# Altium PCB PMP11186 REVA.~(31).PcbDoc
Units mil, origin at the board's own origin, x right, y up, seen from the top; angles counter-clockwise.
Board outline 5750 x 3370 mil, 4 copper layers (Top Layer, Signal Layer 1, Signal Layer 2, Bottom Layer), stack 85.4 mil thick; 92 components, 39 nets, 228 pads, 139 vias.
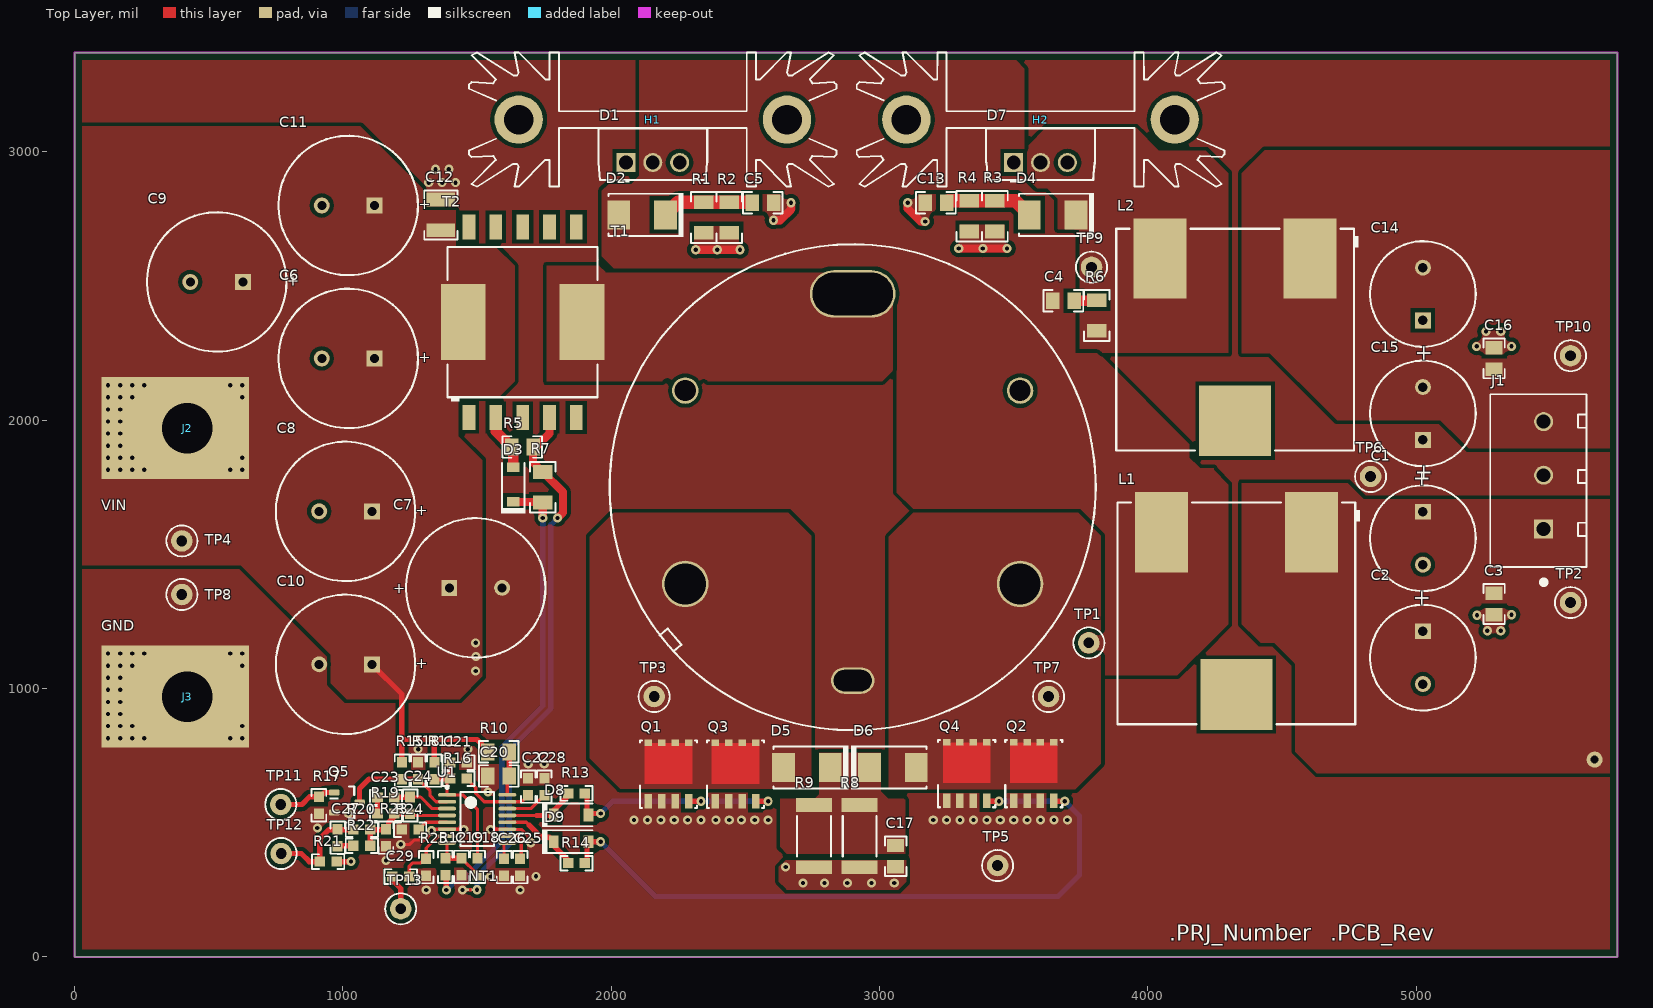
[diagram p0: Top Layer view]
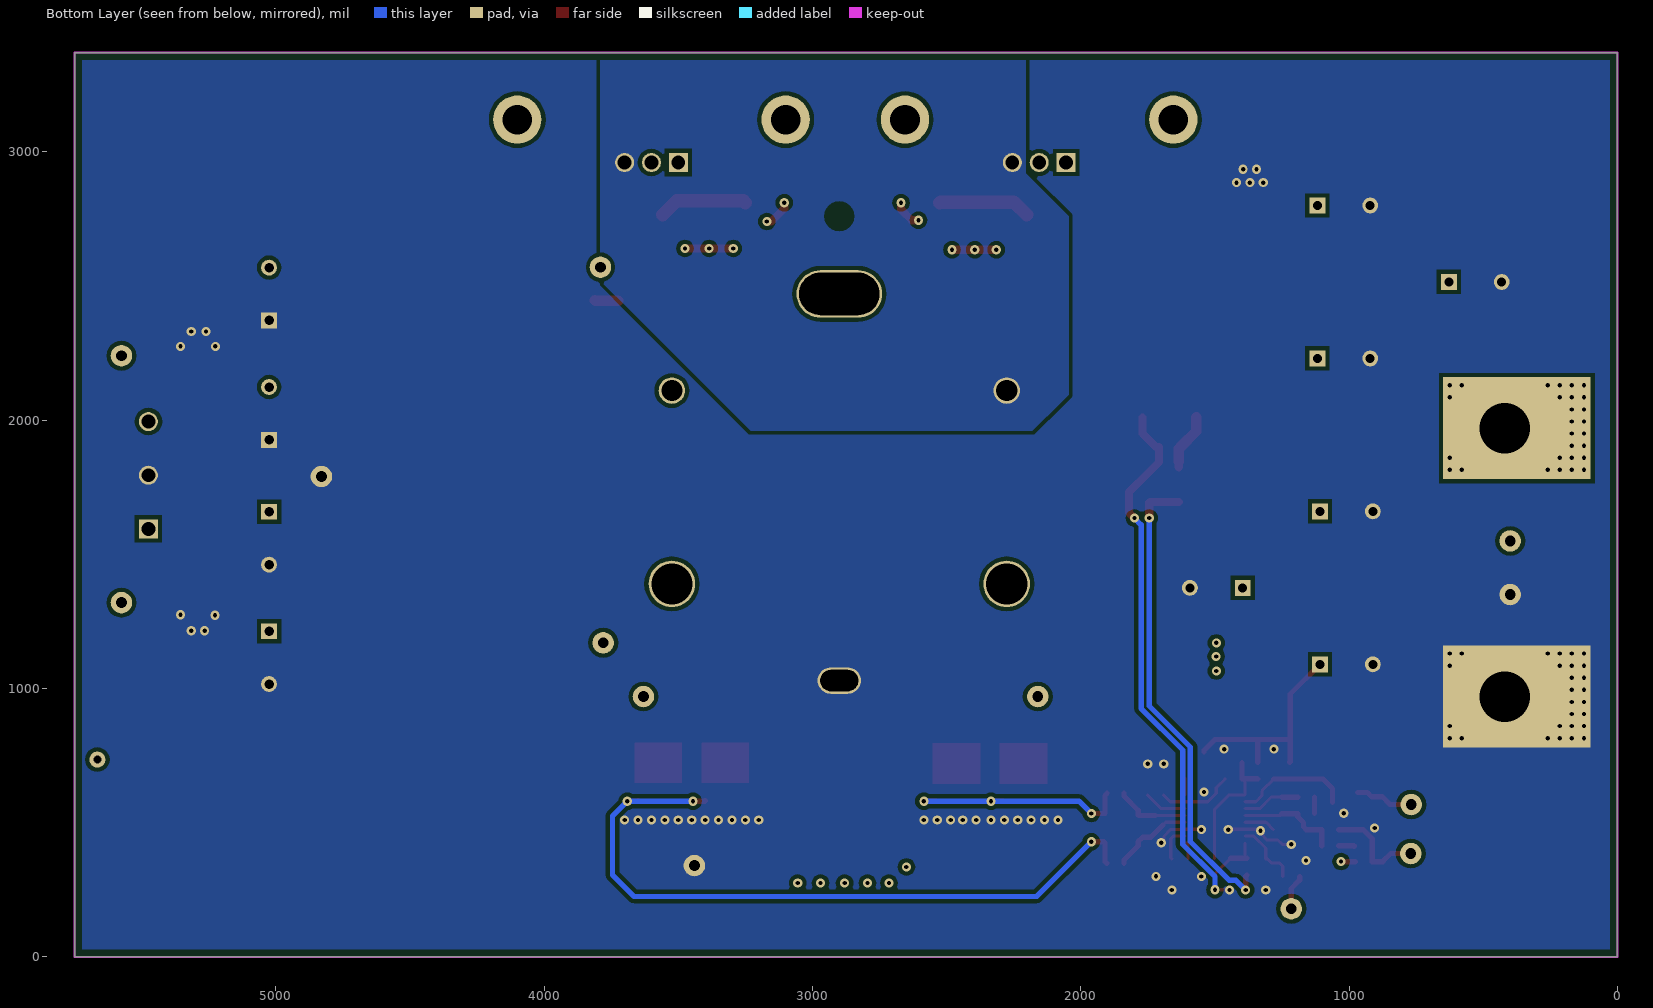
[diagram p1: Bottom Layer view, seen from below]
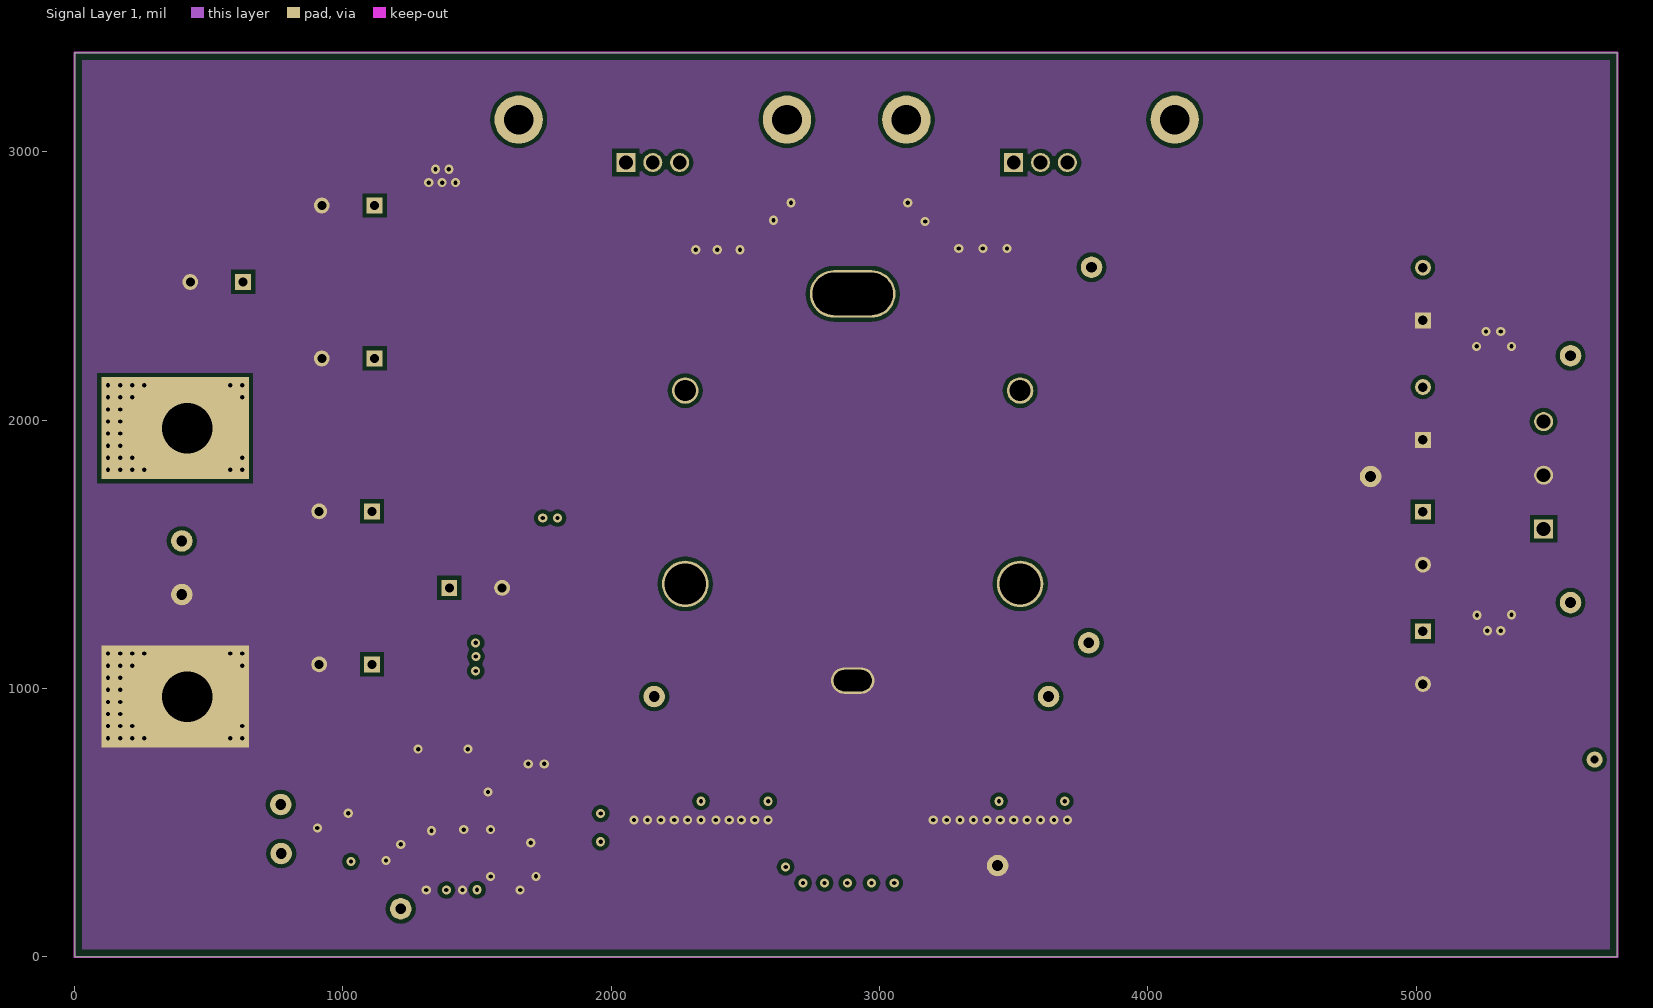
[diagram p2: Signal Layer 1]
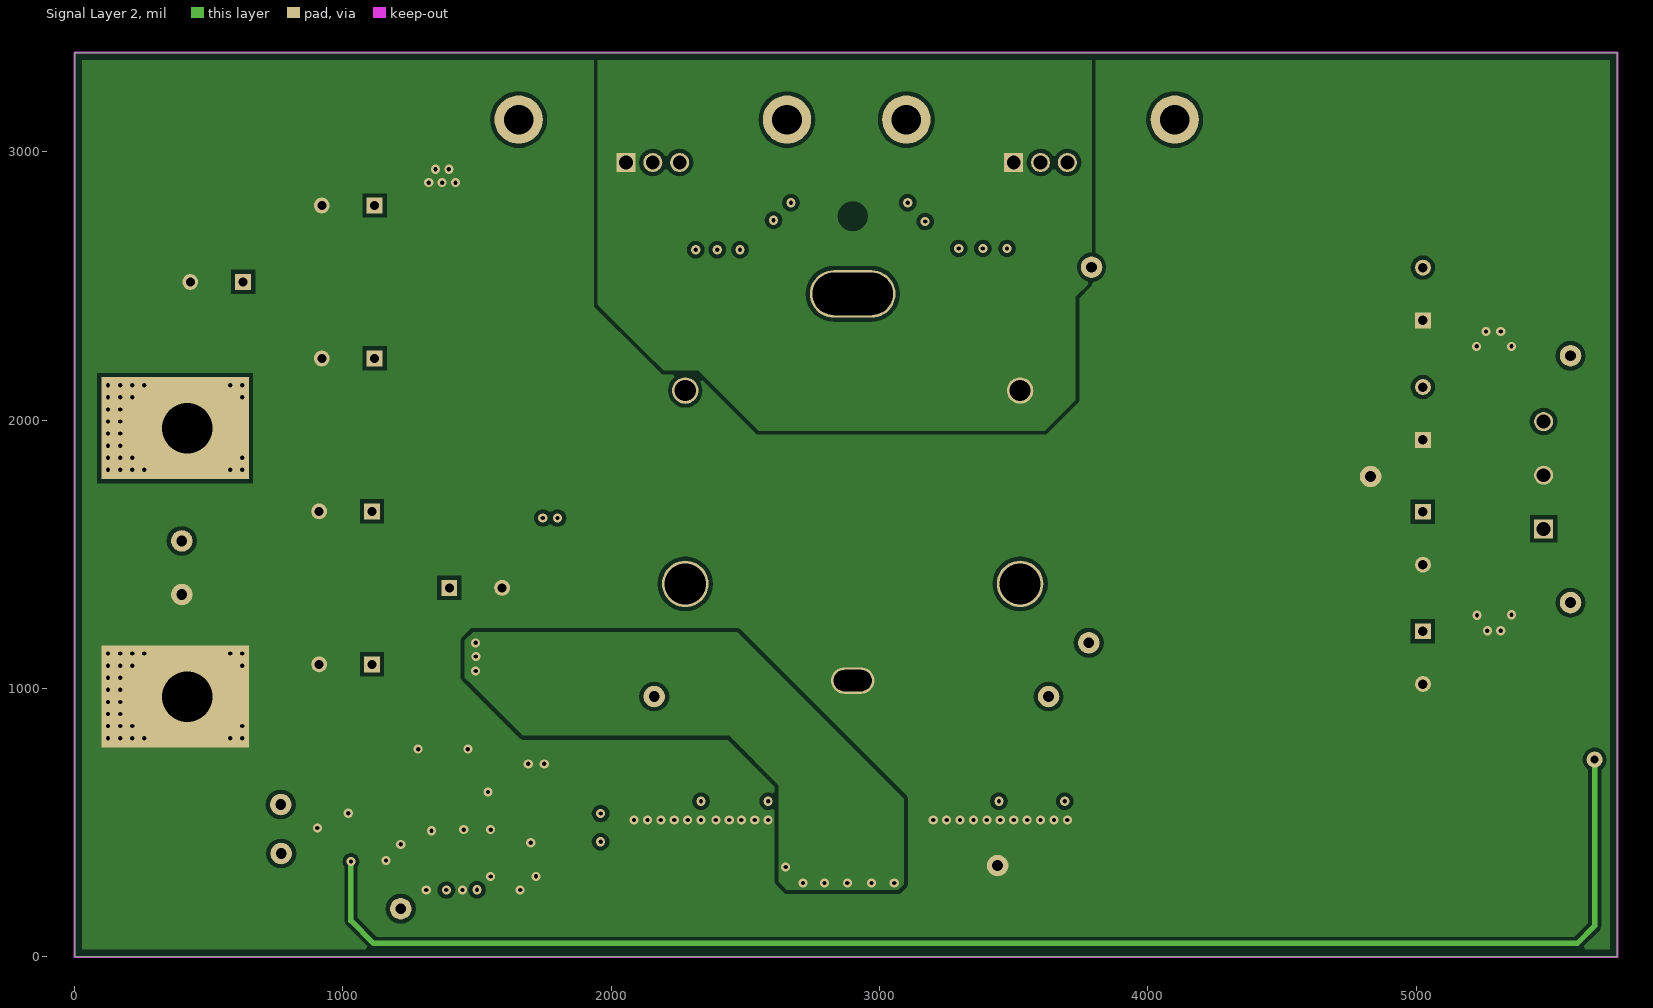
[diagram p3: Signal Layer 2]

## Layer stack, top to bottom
Top Solder: solder mask 0.4, Solder Resist, Dk 3.5
Top Layer: signal copper 2.8
Dielectric1: core 59.2, FR-4, Dk 4.8
Signal Layer 1: signal copper 2.8
Dielectric 3: prepreg 5, Dk 4.2
Signal Layer 2: signal copper 2.8
Dielectric 2: core 10, Dk 4.2
Bottom Layer: signal copper 2.8
Bottom Solder: solder mask 0.4, Solder Resist, Dk 3.5

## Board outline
0,0 5750,0 5750,3370 0,3370

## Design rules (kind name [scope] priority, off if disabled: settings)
AcuteAngle [All] p1: minimum=4.50000000000000E+0001 checktracksonly=FALSE
AssemblyTestPointUsage [All] p1: valid=2
Clearance Clearance_Keepouts [((IsTrack Or IsArc) And Not InPoly) And IsFree and IsKeepOut vs ((IsTrack Or IsArc) And Not InPoly) And IsFree and IsKeepOut] p1: gap=0
Clearance Clearance_BoardEdge_MountingHoles [OnCopper and InComponentClass('Mounting Holes') vs IsKeepOut] p2: gap=40
Clearance Clearance_BoardEdge_Poly [OnCopper and InPoly vs IsKeepOut] p3: gap=25
Clearance Clearance_BoardEdge [OnCopper and Not InComponentClass('Logo') and not InComponentClass('FiducialMark') and not InRegion(1000,500,4000,800) and Not IsKeepout vs IsKeepOut] p4: gap=25
Clearance Clearance_Poly [InPolygon] p5: gap=15
Clearance [All] p6: gap=7.87
ComponentClearance ComponentClearance_MountingHoles_FiducialMarks [InComponentClass('Mounting Holes') vs InComponentClass('FiducialMark')] p1: gap=50 collisioncheckmode=3 verticalgap=10 showdistances=FALSE
ComponentClearance ComponentClearance_Shunt [InComponentClass('Header') vs InComponentClass('Shunt')] p2: gap=0 collisioncheckmode=3 verticalgap=0 showdistances=FALSE
ComponentClearance ComponentClearance_Logo [InComponentClass('Logo')] p3: gap=50 collisioncheckmode=3 verticalgap=10 showdistances=FALSE
ComponentClearance ComponentClearance_ScrewToNut [(HasFootprint('NY PMS 440 0025 PH')) vs (HasFootprint('Keystone_1902C'))] p4: gap=5 collisioncheckmode=3 verticalgap=10 showdistances=FALSE
ComponentClearance ComponentClearance_MountingHoles [InComponentClass('Mounting Holes')] p5: gap=150 collisioncheckmode=3 verticalgap=100000 showdistances=FALSE
ComponentClearance ComponentClearance_SmallPassives [HasFootprint('0201*') or HasFootprint('0402*') or HasFootprint('0508') or HasFootprint('0603*') or HasFootprint('0612') or HasFootprint('0805*') or HasFootprint('0815*') or HasFootprint('0830*') or HasFootprint('1206*') or HasFootprint('1210*') or HasFootprint('1808*') or HasFootprint('1812*') or HasFootprint('1825*') or HasFootprint('2010*') or HasFootprint('2220*') or HasFootprint('2225*') or HasFootprint('2512*') or HasFootprint('2728*') or HasFootprint('3518*') vs HasFootprint('0201*') or HasFootprint('0402*') or HasFootprint('0508') or HasFootprint('0603*') or HasFootprint('0612') or HasFootprint('0805*') or HasFootprint('0815*') or HasFootprint('0830*') or HasFootprint('1206*') or HasFootprint('1210*') or HasFootprint('1808*') or HasFootprint('1812*') or HasFootprint('1825*') or HasFootprint('2010*') or HasFootprint('2220*') or HasFootprint('2225*') or HasFootprint('2512*') or HasFootprint('2728*') or HasFootprint('3518*')] p6: gap=15 collisioncheckmode=3 verticalgap=10 showdistances=FALSE
ComponentClearance ComponentClearance_THtoSMT [IsThruComponent vs IsSMTComponent] p7: gap=25 collisioncheckmode=3 verticalgap=30 showdistances=FALSE
ComponentClearance ComponentClearance_THtoTH [IsThruComponent vs IsThruComponent] p8: gap=25 collisioncheckmode=3 verticalgap=30 showdistances=FALSE
ComponentClearance [All] p9: gap=25 collisioncheckmode=3 verticalgap=10 showdistances=FALSE
DiffPairsRouting [All] p1: maxlimit=100 minlimit=10 mostfreqgap=10 toplayer_minwidth=15 toplayer_maxwidth=15 toplayer_prefwidth=15 midlayer1_minwidth=15 midlayer1_maxwidth=15 midlayer1_prefwidth=15 midlayer2_minwidth=15 midlayer2_maxwidth=15 midlayer2_prefwidth=15 bottomlayer_minwidth=15 bottomlayer_maxwidth=15 bottomlayer_prefwidth=15 maxuncoupledlength=1000
FabricationTestPointUsage TestPointUsage [All] p1: valid=2 allowmultiple=FALSE
FabricationTestpoint Testpoint [All] p1: side=3 testpointundercomponent=TRUE minsize=40 maxsize=100 preferedsize=60 minholesize=0 maxholesize=40 preferedholesize=32 testpointgrid=1 allowsidetop=TRUE allowsidebottom=TRUE usegrid=TRUE gridtolerance=0.01
FanoutControl Fanout_LCC [IsLCC] p1: bgadir=Out bgaviamode=Centered fanoutstyle=Auto fanoutdirection=Alternating viagrid=1 // Fanout_LCC (Default Rule)
FanoutControl Fanout_BGA [IsBGA] p2: bgadir=Out bgaviamode=Centered fanoutstyle=Auto fanoutdirection=Alternating viagrid=1 // Fanout_BGA (Default Rule)
FanoutControl Fanout_Default [All] p4: bgadir=Out bgaviamode=Centered fanoutstyle=Auto fanoutdirection=Alternating viagrid=1 // Fanout_Default (Default Rule)
FanoutControl Fanout_Small [(CompPinCount < 5)] p5: bgadir=Out bgaviamode=Centered fanoutstyle=Auto fanoutdirection=OutThenIn viagrid=1 // Fanout_Small (Default Rule)
HoleSize [All] p1: absolutevalues=TRUE maxlimit=251 minlimit=8 maxpercent=80.000 minpercent=20.000
MinimumAnnularRing MinimumAnnularRing_ThermalPadVias [IsVia and InAnyComponent] p1: minimumring=5.91
MinimumAnnularRing [All] p2: minimumring=9
MinimumSolderMaskSliver MinimumSolderMaskSliver_Logo [InComponentClass('Logo') vs InComponentClass('Logo')] p1: minsoldermaskwidth=0.7
MinimumSolderMaskSliver [All] p2: minsoldermaskwidth=3.94
PlaneClearance [All] p1: clearance=12
PlaneConnect [All] p1: planeconnectstyle=Direct reliefexpansion=10 reliefentries=4 reliefconductorwidth=10 reliefairgap=10
PolygonConnect [All] p1: connectstyle=Direct reliefconductorwidth=10 reliefentries=4 polygonreliefangle="90 Angle" airgapwidth=10
RoutingVias ThermalPadVias [IsVia and InAnyComponent] p1: holewidth=7.87 width=19.68 viastyle="Through Hole" minholewidth=7.87 minwidth=19.68 maxholewidth=12.99 maxwidth=23.62
RoutingVias [All] p2: holewidth=16 width=34 viastyle="Through Hole" minholewidth=7.87 minwidth=26 maxholewidth=40 maxwidth=65
SilkToBoardRegionClearance [Not ((IsComment or IsDesignator) And (Hide <> 'False')) and not InRegion(1000,500,4000,800)] p1:
SilkToSilkClearance SilkToSilkClearance_Pb-FreeLogo [(HasFootprint('Pb-Free_Overlay_Medium') OR HasFootprint('Pb-Free_Overlay_Small')) vs (HasFootprint('Pb-Free_Overlay_Medium') OR HasFootprint('Pb-Free_Overlay_Small'))] p1: silktosilkclearance=0
SilkToSilkClearance [All] p2: silktosilkclearance=0
SilkToSolderMaskClearance "Silk to Solder Mask Opening" [All] p1: minsilkscreentomaskgap=1 clearancetoexposedcopper=FALSE
SolderMaskExpansion [All] p1: expansion=1.97
UnpouredPolygon [All] p1: allowunpoured=FALSE
Width [All] p1: maxlimit=100 minlimit=6 preferedwidth=10 checkconnectedcopper=TRUE
13 further rules are at their usual default settings.

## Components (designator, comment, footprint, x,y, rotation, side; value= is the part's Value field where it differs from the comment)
C1 "35ZL470MEFC10X20" CAPPR5-10X20 5025,1560 r270 top
C2 "35ZL470MEFC10X20" CAPPR5-10X20 5025,1115 r270 top
C3 "GRM21BR71H105KA12L" 0805_HV 5290,1315 r270 top
C4 "GRM21A5C2E101JW01D" 0805_HV 3685,2445 r0 top
C5 "C2012X7R2A103M" 0805_HV 2565,2810 r0 top
C6 "25ZLH2700M12.5X35" ZLH_1250x2500 1020,2230 r180 top
C7 "25ZLH2700M12.5X35" ZLH_1250x2500 1495,1375 r0 top
C8 "25ZLH2700M12.5X35" ZLH_1250x2500 1010,1660 r180 top
C9 "25ZLH2700M12.5X35" ZLH_1250x2500 530,2515 r180 top
C10 "25ZLH2700M12.5X35" ZLH_1250x2500 1010,1090 r180 top
C11 "25ZLH2700M12.5X35" ZLH_1250x2500 1020,2800 r180 top
C12 "C3225X7R1E106M" 1210 1365,2765 r90 top
C13 "C2012X7R2A103M" 0805_HV 3210,2810 r0 top
C14 "35ZL470MEFC10X20" CAPPR5-10X20 5025,2470 r90 top
C15 "35ZL470MEFC10X20" CAPPR5-10X20 5025,2025 r90 top
C16 "GRM21BR71H105KA12L" 0805_HV 5290,2230 r270 top
C17 "C2012X7R2A103M" 0805_HV 3060,375 r90 top
C18 "C1608C0G1H152J" 0603 1501.98,335.31 r270 top
C19 "C1608C0G1H101J" 0603 1441.98,335.31 r90 top
C20 "C2012X7R1E105K" 0805_HV 1580.68,674.01 r180 top
C21 "" 0603 1430.68,724.01 r180 top
C22 "C1608X7R1C105K" 0603 1690.68,634.01 r270 top
C23 "C1608X7R1H473K" 0603 1160.68,594.01 r0 top
C24 "C1608C0G1H150J" 0603 1250.68,564.01 r270 top
C25 "C1608X7R1C105K" 0603 1660.68,334.01 r270 top
C26 "C1608X7R1H103K" 0603 1600.68,334.01 r270 top
C27 "" 0603 980.68,444.01 r90 top
C28 "C1608X7R1C105K" 0603 1750.68,634.01 r90 top
C29 "C1608C0G1H101J" 0603 1215.68,299.01 r0 top
D1 "FML22S" ITO-220AB 2155,2960 r0 top
D2 "MURS120-13-F" SMB 2115,2765 r180 top
D3 "MMSD4148T1G" SOD-123 1635,1760 r90 top
D4 "MURS120-13-F" SMB 3645,2765 r180 top
D5 "MURS120-13-F" SMB 2729.45,705.28 r180 top
D6 "MURS120-13-F" SMB 3049.45,705.28 r0 top
D7 "FML22R" ITO-220AB 3600,2960 r0 top
D8 "BAT54T1G" SOD-123 1850.68,529.01 r0 top
D9 "BAT54T1G" SOD-123 1850.68,429.01 r0 top
H1 "513201B02500G" HSINK_513201B02500 2155,3120 r0 top
H2 "513201B02500G" HSINK_513201B02500 3600,3120 r0 top
J1 "OSTTA034163" On-Shore_OSTTA034163 5455,1775 r90 top
J2 "CB35-36-CY" CB35-36-CY 420,1970 r0 top
J3 "CB35-36-CY" CB35-36-CY 420,970 r0 top
L1 "B82559A0353A020" B82559_1420 4330,1280 r270 top
L2 "B82559A0353A020" B82559_1420 4325,2300 r270 top
NT1 "Net-Tie" Net-Tie_10mil 1475,250 r180 top net-tie
Q1 "DNP" TRANS_NexFET_Q5B 2213.12,688.44 r90 top
Q2 "DNP" TRANS_NexFET_Q5B 3574.72,690.58 r90 top
Q3 "CSD18540Q5B" TRANS_NexFET_Q5B 2463.12,688.44 r90 top
Q4 "CSD18540Q5B" TRANS_NexFET_Q5B 3324.72,690.58 r90 top
Q5 "2N7002P,215" SOT-23 1015,575 r0 top
R1 "" 1206 2345,2755 r90 top
R2 "CRCW120649K9FKEA" 1206 2440,2755 r90 top
R3 "" 1206 3430,2760 r270 top
R4 "CRCW120649K9FKEA" 1206 3335,2760 r270 top
R5 "CRCW08051K00FKEA" 0805_HV 1668.74,1900 r0 top
R6 "CRCW1206100RFKEA" 1206 3810,2390 r90 top
R7 "CSR1206FKR750" 1206 1745,1750 r270 top
R8 "" 2512 2925.68,449.81 r270 top
R9 "CRCW251210K0JNEG" 2512 2755.68,449.81 r270 top
R10 "ERJ-6GEYJ4R7V" 0805_HV 1580.68,764.01 r180 top
R11 "" 0603 1340.68,694.01 r270 top
R12 "CRCW06031K00FKEA" 0603 1381.98,335.31 r270 top
R13 "CRCW06031R00FKEA" 0603 1870.68,609.01 r0 top
R14 "CRCW06031R00FKEA" 0603 1870.68,349.01 r0 top
R15 "CRCW0603130KFKEA" 0603 1220.68,694.01 r90 top
R16 "CRCW0603200KFKEA" 0603 1430.68,664.01 r180 top
R17 "CRCW060310K0FKEA" 0603 910.89,565 r90 top
R18 "CRCW060321K0FKEA" 0603 1280.68,694.01 r270 top
R19 "CRCW0603100KFKEA" 0603 1160.68,534.01 r180 top
R20 "CRCW060347K5FKEA" 0603 1070.68,474.01 r180 top
R21 "CRCW060349R9FKEA" 0603 945,355 r180 top
R22 "" 0603 1070.68,414.01 r180 top
R23 "CRCW06032K49FKEA" 0603 1160.68,444.01 r90 top
R24 "CRCW060349K9FKEA" 0603 1250.68,474.01 r0 top
R25 "CRCW060329K4FKEA" 0603 1310.68,334.01 r90 top
T1 "G154027ALF" GCI_G154027ALF 2900,1750 r90 top
T2 "G154028ALF" GCI_G154028ALF 1670,2365 r90 top
TP1 "5000" Keystone5000 3780,1170 r0 top
TP2 "5000" Keystone5000 5575,1320 r0 top
TP3 "5000" Keystone5000 2160,970 r0 top
TP4 "5000" Keystone5000 400,1550 r0 top
TP5 "5001" Keystone5001 3440,340 r0 top
TP6 "5001" Keystone5001 4830,1790 r0 top
TP7 "5000" Keystone5000 3630,970 r0 top
TP8 "5001" Keystone5001 400,1350 r0 top
TP9 "5000" Keystone5000 3790,2570 r0 top
TP10 "5000" Keystone5000 5575,2240 r0 top
TP11 "5000" Keystone5000 768.65,567.6 r0 top
TP12 "5000" Keystone5000 770,385 r0 top
TP13 "5000" Keystone5000 1215.68,179.01 r0 top
U1 "LM25037QMT" MTC16_N 1500.68,514.01 r0 top

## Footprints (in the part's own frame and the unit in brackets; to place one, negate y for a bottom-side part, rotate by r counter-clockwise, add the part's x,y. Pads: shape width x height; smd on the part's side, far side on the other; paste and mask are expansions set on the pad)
0603 [mm] "0603 from SM-752 data"
  rect 1x0.95 smd: 1(-0.8,0) 2(0.8,0)
  silkscreen extent -1.52,-0.69 1.52,0.69, body extent -0.87,-0.47 0.87,0.47, height 0.85
0805_HV [mil] "0805 with 30mil clearance between pads"
  rect 50x63 smd: 1(-40,0) 2(40,0)
  silkscreen extent -74,-40 74,40, body extent -43,-29 43,29, height 57
1206 [mm] "1206 from SM-752 data"
  rect 1.3x1.85 smd: 1(-1.45,0) 2(1.45,0)
  silkscreen extent -2.4,-1.21 2.4,1.21, body extent -1.7,-0.9 1.7,0.9, height 1.35
1210 [mm] "1210 from SM-752 data"
  rect 1.3x2.7 smd: 1(-1.45,0) 2(1.45,0)
  silkscreen extent -2.32,-1.57 2.32,1.57, body extent -1.7,-1.35 1.7,1.35, height 1.35
2512 [mm] "Chip Resistor, Body 6.3x3.2mm, IPC Medium Density"
  rect 1.3x3.4 smd: 1(-2.95,0) 2(2.95,0)
  silkscreen extent -1.9,-1.6 1.9,1.6, body extent -3.22,-1.67 3.22,1.67, height 0.71
B82559_1420 [mm] "SMD, 3-Leads, Body 21.5x21mm"
  rect 7.6x5 smd: 1(-7.675,7.1) 2(-7.675,-7.1)
  rect 6.7x6.8 smd: 3(7.675,0)
  silkscreen extent -10.5,-11.25 10.5,11.7, body extent -11,-11.25 11,11.25, height 14.2
CAPPR5-10X20 [mm] "Capacitor, Electrolytic, Radial; Body 10 x 20 mm (Dia.xH typ); Pin Spacing 5 mm (typ)"
  rect 1.5x1.5 hole 0.9: 1(-2.5,0)
  round 1.5 hole 0.9: 2(2.5,0)
  silkscreen extent -5,-5 5,5, body extent -5.01,-5.01 5.01,5.01, height 22
CB35-36-CY [mil] "Terminal 50A Lug"
  rect 550x380 hole 188 copper offset -45,0 paste-190: 1(0,0)
  body extent -960,-189 230,191, height 614
GCI_G154027ALF [mm] "TH, 6-Leads, Dia 46mm"
  round 4.4 hole 3.9: 1(-9.15,15.848) 3(-9.15,-15.848)
  oval 2.5x4.1 hole 2 slot 3.6 at 90 deg: 2(-18.3,0)
  round 2.5 hole 2: 4(9.15,-15.848) 6(9.15,15.848)
  oval 4.5x8.1 hole 4 slot 7.6 at 90 deg: 5(18.3,0)
  silkscreen extent -23,-23 23,23, body extent -23.01,-23.01 23.01,23.01, height 28
GCI_G154028ALF [mm] "SMD, 12-Leads, Body 14.2x20mm, Pitch 2.54mm"
  rect 2.35x1.2 smd: 1(-9.025,5.08) 2(-9.025,2.54) 3(-9.025,0) 4(-9.025,-2.54) 5(-9.025,-5.08) 6(9.025,-5.08) 7(9.025,-2.54) 8(9.025,0) 9(9.025,2.54) 10(9.025,5.08)
  rect 7.2x4.25 smd: 11(0,5.625) 12(0,-5.625)
  silkscreen extent -7.5,-7.1 7.1,7.1, body extent -10,-7.25 10,7.25, height 10.52
HSINK_513201B02500 [mil] "Aavid"
  round 180 hole 110.24: 1(-500,0) 2(500,0)
  silkscreen extent -685,-250 685,250, body extent -685,-250 685,250, height 2000
ITO-220AB [mm] "TH, 3-Leads, Body 10.11x15.87mm, Pitch 2.54mm"
  rect 1.8x1.8 hole 1.3: 1(-2.54,0)
  round 1.8 hole 1.3: 2(0,0) 3(2.54,0)
  silkscreen extent -5.16,-1.9 5.15,3.24, body extent -5.16,-1.66 5.16,3.24, height 19.67
Keystone5000 [mil] "For Keystone 500x miniature loop terminals"
  round 80 hole 40: 1(0,0)
  silkscreen extent -58,-58 58,58, body extent -49,-49 49,49, height 182
Keystone5001 [mil] "For Keystone 500x miniature loop terminals"
  round 80 hole 40: 1(0,0)
  silkscreen extent -58,-58 58,58, body extent -49,-49 49,49, height 182
MTC16_N [mm] "TSOP, 16-Leads, Body 5x4.4mm, Pitch 0.65mm, IPC Medium Density"
  oval 1.7x0.35 smd: 1(-2.85,2.275) 2(-2.85,1.625) 3(-2.85,0.975) 4(-2.85,0.325) 5(-2.85,-0.325) 6(-2.85,-0.975) 7(-2.85,-1.625) 8(-2.85,-2.275) 9(2.85,-2.275) 10(2.85,-1.625) 11(2.85,-0.975) 12(2.85,-0.325) 13(2.85,0.325) 14(2.85,0.975) 15(2.85,1.625) 16(2.85,2.275)
  silkscreen extent -2.97,-2.55 1.6,3.12, body extent -2.25,-2.55 2.25,2.55, height 1.1
Net-Tie_10mil [mil] "10mil net tie, no solder mask opening, no solder paste"
  rect 10x10 smd paste-5 mask-5: 1(-10,0) 2(10,0)
  Top Layer region: -6,5 6,5 6,-5 -6,-5
On-Shore_OSTTA034163 [mm] "TERM BLOCK 3x1, 5.08mm, TH"
  rect 1.8x1.8 hole 1.3: 1(-4.58,-0.5)
  round 1.8 hole 1.3 paste+0: 2(0.5,-0.5) 3(5.58,-0.5)
  silkscreen extent -9.73,-4.55 8.17,4.55, body extent -8.22,-4.6 8.22,4.6, height 13
SMB [mil] "Molded Diode, 2-Leads, Body 5.4x3.6mm, IPC Medium Density, based on OnSemi component dimensions"
  rect 85x107.99 smd: 1(-87.01,0) 2(87.01,0)
  silkscreen extent -155,-82 125,82, body extent -106,-71 106,71, height 91
SOD-123 [mm] "On Semi recommended land pattern"
  rect 0.915x1.22 smd: 1(-1.637,0) 2(1.637,0)
  silkscreen extent -2.74,-1.17 2.03,1.17, body extent -1.93,-0.9 1.93,0.9, height 1.35
SOT-23 [mm] "SOT23, 3-Leads, Body 2.9x1.3mm, Pitch 0.95mm, Lead Span 2.5mm, IPC Medium Density"
  rrect50% 1x0.6 smd: 1(-1.2,0.95) 2(-1.2,-0.95) 3(1.2,0)
  silkscreen extent -1.63,-1.5 0.7,1.5, body extent -1.16,-1.45 1.21,1.45, height 1
TRANS_NexFET_Q5B [mm] "TI recommended land pattern (nominal) November 2012"
  rect 1.372x0.71 smd paste-0.4: 1(-2.776,1.905) 2(-2.776,0.635) 3(-2.776,-0.635) 4(-2.776,-1.905)
  rect 0.59x0.71 smd paste-0.3: 5(2.776,-1.905) 6(2.776,-0.635) 7(2.776,0.635) 8(2.776,1.905)
  Top Layer region: -1.106,-2.26 2.744,-2.26 2.744,2.26 -1.106,2.26
  silkscreen extent -3.38,-2.7 3,2.7, body extent -3.23,-2.55 2.87,2.55, height 1.06
ZLH_1250x2500 [mm] "Rubycon"
  rect 1.5x1.5 hole 0.85: 1(-2.5,0)
  round 1.5 hole 0.85: 2(2.5,0)
  silkscreen extent -6.6,-6.6 6.6,6.6, body extent -6.45,-6.49 6.49,6.49, height 26.51

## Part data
C1 C2 C14 C15: "CAP, AL, 470 µF, 35 V, 0.023 Ohms, 1.82A, TH"
C3 C16: "CAP, CERM, 1uF, 50V, +/-10%, X7R, 0805"
C4: "CAP, CERM, 100 pF, 250 V, +/- 5%, C0G/NP0, 0805"
C5 C13 C17: "CAP, CERM, 0.01 µF, 100 V, +/- 20%, X7R, 0805"
C6 C7 C8 C9 C10 C11: library part 63ZLH470M12.5X25, "CAP, AL, 2700 µF, 25 V, 0.016 ohm, 4.12A, TH"
C12: "CAP, CERM, 10 µF, 25 V, +/- 20%, X7R, 1210"
C18: "CAP, CERM, 1500 pF, 50 V, +/- 5%, C0G/NP0, 0603"
C19 C29: "CAP, CERM, 100 pF, 50 V, +/- 5%, C0G/NP0, 0603"
C20: "CAP, CERM, 1 µF, 25 V, +/- 10%, X7R, 0805"
C21 C27: library part C1608C0G1H271J, "CAP, DNP, 0603"
C22 C25 C28: "CAP, CERM, 1 µF, 16 V, +/- 10%, X7R, 0603"
C23: "CAP, CERM, 0.047 µF, 50 V, +/- 10%, X7R, 0603"
C24: "CAP, CERM, 15 pF, 50 V, +/- 5%, C0G/NP0, 0603"
C26: "CAP, CERM, 0.01 µF, 50 V, +/- 10%, X7R, 0603"
D1 D7: "Diode, Ultrafast, 200 V, 10 A, TH"
D2 D4 D5 D6: "Diode, Superfast Rectifier, 200 V, 1 A, SMB"
D3: "Diode, Switching, 100 V, 0.2 A, SOD-123"
D8 D9: "Diode, Schottky, 30V, 0.2A, SOD-123"
H1 H2: "HEATSINK TO-218/TO-247 W/PINS 2\""
J1: "Terminal Block, 3x1, 5.08 mm, TH"
J2 J3: "Terminal 50A Lug"
L1 L2: "Inductor, Wirewound, Ferrite, 35 µH, 9.3 A, 0.007 ohm, SMD"
NT1: "Single point connection between nets."
Q1 Q2: library part CSD18540Q5B, "MOSFET, DNP, SON 5x6mm"
Q3 Q4: "MOSFET, N-CH, 60 V, 28 A, SON 5x6mm"
Q5: "MOSFET, N-CH, 60 V, 0.36 A, SOT-23"
R1 R3: library part CRCW120649K9FKEA, "RES, DNP, 1206"
R2 R4: "RES, 49.9 k, 1%, 0.25 W, 1206"
R5: "RES, 1.00 k, 1%, 0.125 W, 0805"
R6: "RES, 100 ohm, 1%, 0.25W, 1206"
R7: "RES, 0.75, 1%, 0.5 W, 1206"
R8: library part CRCW251210K0JNEG, "RES, DNP, 2512"
R9: "RES, 10 k, 5%, 1 W, 2512"
R10: "RES, 4.7, 5%, 0.125 W, 0805"
R11 R22: library part CRCW060332K4FKEA, "RES, DNP, 0603"
R12: "RES, 1.00 k, 1%, 0.1 W, 0603"
R13 R14: "RES, 1.00 ohm, 1%, 0.1W, 0603"
R15: "RES, 130 k, 1%, 0.1 W, 0603"
R16: "RES, 200 k, 1%, 0.1 W, 0603"
R17: "RES, 10.0k ohm, 1%, 0.1W, 0603"
R18: "RES, 21.0 k, 1%, 0.1 W, 0603"
R19: "RES, 100 k, 1%, 0.1 W, 0603"
R20: "RES, 47.5 k, 1%, 0.1 W, 0603"
R21: "RES, 49.9, 1%, 0.1 W, 0603"
R23: "RES, 2.49k ohm, 1%, 0.1W, 0603"
R24: "RES, 49.9 k, 1%, 0.1 W, 0603"
R25: "RES, 29.4 k, 1%, 0.1 W, 0603"
T1: "Transformer, 50 uH, TH"
T2: "Transformer, 22.4 mH, SMT"
TP1 TP2 TP3 TP4 TP7 TP9 TP10 TP11 TP12 TP13: "Test Point, Miniature, Red, TH"
TP5 TP6 TP8: "Test Point, Miniature, Black, TH"
U1: "Dual-Mode PWM Controller With Alternating Outputs, Automotive Grade, 16-pin TSSOP"

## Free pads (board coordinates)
  round 60 hole 30: 0(5665,735)

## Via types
v1: diameter 34, hole 16, Top Layer to Bottom Layer, 83 vias
v2: diameter 32, hole 16, Top Layer to Bottom Layer, 56 vias

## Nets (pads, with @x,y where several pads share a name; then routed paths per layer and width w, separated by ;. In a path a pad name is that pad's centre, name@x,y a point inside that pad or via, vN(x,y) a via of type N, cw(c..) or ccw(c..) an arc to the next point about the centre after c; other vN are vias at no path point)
GND: C1.2 C2.2 C3.2 C5.2 C6.2 C7.2 C8.2 C9.2 C10.2 C11.2 C12.2 C13.1 C14.1 C15.1 C16.1 C19.1 C20.2 C21.1 C22.1 C25.2 C26.2 C28.2 J1.2 J3.1 NT1.2 Q1.1 Q1.2 Q1.3 Q2.1 Q2.2 Q2.3 Q3.1 Q3.2 Q3.3 Q4.1 Q4.2 Q4.3 Q5.2 R1.1 R2.1 R3.2 R4.2 R17.1 R18.1 R23.1 R24.1 R25.1 T1.2 TP5.1 TP6.1 TP8.1 U1.6 U1.11 | length 1022.5
  Top Layer w12: v1(1215.68,419.01) 1249.01,419.01 1265,435 1305,435 1330,460 v1(1330,470) 1335.63,475.63 U1.6 1449.07,475.63 v1(1450.68,474.01) ; v1(1445.68,249.01) 1446.67,250 NT1.2 ; v1(1550.68,474.01) 1552.3,475.63 U1.11 1613.52,475 1665,475 1690,450 1690,435 v1(1700,425)
  Top Layer w30: v1(2315,2635) v1(2480,2635) ; v1(2605,2745) 2630,2745 2670,2785 v1(2670,2810) ; v1(3105,2810) 3105,2788.6 3153.6,2740 v1(3170,2740) ; v1(3295,2640) v1(3385,2640) v1(3475,2640)
  other v1: 1310.68,249.01 1660.68,249.01 1550.68,299.01 1720,300 1160.68,359.01 905,480 2085,510 2135,510 2185,510 2235,510 2285,510 2335,510 2390,510 2440,510 2485,510 2535,510 2585,510 3200,510 3250,510 3300,510 3350,510 3400,510 3450,510 3500,510 3550,510 3600,510 3650,510 3700,510 1020,535 1540.68,614.01 1690.68,719.01 1750.68,719.01 1280.68,774.01 1465.68,774.01 5265,1215 5315,1215 5226.59,1272.95 5355,1275 5225,2275 5355,2275 5260,2330 5315,2330 2395,2635 1320,2885 1370,2885 1420,2885 1345,2935 1395,2935
  other v2: 125,815 170,815 215,815 260,815 580,815 625,815 125,860 170,860 215,860 625,860 125,905 170,905 125,950 170,950 125,995 170,995 125,1040 170,1040 125,1085 170,1085 215,1085 625,1085 125,1130 170,1130 215,1130 260,1130 580,1130 625,1130
NetC4_1: C4.1 D1.2 D2.2 L1.2 TP1.1
NetC4_2: C4.2 R6.2 | length 85.9
  Top Layer w40: C4.2 3807.91,2445 R6.2
NetC5_1: C5.1 D2.1 R1.2 R2.2 | length 343.4
  Top Layer w50: D2.1 2249.09,2812.09 R1.2 R2.2 2522.91,2812.09 C5.1
NetC6_1: C6.1 C7.1 C8.1 C9.1 C10.1 C11.1 C12.1 C17.1 J2.1 R8.2 R9.2 R10.2 R11.1 R15.2 T2.11 TP4.1 | length 838.6
  Top Layer w20: C10.1 1220,978.43 1220,810 ; R15.2 1220,726.19 1220,810 ; R11.1 1340.68,809.32 1340,810 ; R10.2 1540.68,769.32 1500,810 1340,810 ; 1220,810 1340,810
  other v1: 2715,275 2795,275 2880,275 2970,275 3055,275 2650,335 1495,1065 1495.72,1119.52 1495,1170
  other v2: 125,1815 170,1815 215,1815 260,1815 580,1815 625,1815 125,1860 170,1860 215,1860 625,1860 125,1905 170,1905 125,1950 170,1950 125,1995 170,1995 125,2040 170,2040 125,2085 170,2085 215,2085 625,2085 125,2130 170,2130 215,2130 260,2130 580,2130 625,2130
NetC13_2: C13.2 D4.2 R3.1 R4.1 | length 332.5
  Top Layer w50: C13.2 3257.09,2817.09 R4.1 R3.1 3505.91,2817.09 D4.2
NetC14_2: C14.2 C15.2 C16.2 J1.3 L2.1 TP10.1
NetC17_2: C17.2 D5.1 D6.1 R8.1 R9.1
NetC18_1: C18.1 C21.2 R11.2 R16.2 U1.1 | length 501.7
  Top Layer w12: R16.2 1388.48,653.3 U1.1 1446.42,603.58 1501.98,548.02 C18.1
  Top Layer w20: R11.2 1342.18,664.01 R16.2 C21.2
NetC18_2: C18.2 C19.2 R12.1 U1.8 | length 208.2
  Top Layer w12: R12.1 1388.48,373.3 U1.8 ; C19.2 1501.98,306.81 C18.2
  Top Layer w20: R12.1 C19.2
NetC20_1: C20.1 R10.1 U1.16 | length 152.6
  Top Layer w12: U1.16 C20.1@1612.89,666.22
  Top Layer w20: C20.1 R10.1
NetC22_2: C22.2 R16.1 U1.15 | length 286.7
  Top Layer w12: R16.1 1462.18,662.82 1495,630 1495,610 1527.01,577.99 U1.15 1666.16,577.99 C22.2
NetC23_1: C23.1 R19.2 | length 60
  Top Layer w20: R19.2 C23.1
NetC23_2: C23.2 C24.1 U1.3 | length 214.8
  Top Layer w12: C24.1 1289.49,595.51 1332.6,552.4 U1.3
  Top Layer w20: C23.2 1249.19,594.01 C24.1
NetC24_2: C24.2 R19.1 R20.1 R22.1 R23.2 U1.4 | length 390
  Top Layer w12: C24.2 1256.39,526.81 U1.4
  Top Layer w20: R22.1 R20.1 1159.19,474.01 R23.2 1170,484.83 1170,500.47 1192.18,522.65 R19.1 1193.68,532.52 C24.2
NetC25_1: C25.1 U1.10 | length 132.5
  Top Layer w12: U1.10 1654.96,450.04 1665,440 1665,369.83 C25.1
NetC26_1: C26.1 U1.9 | length 68.3
  Top Layer w12: C26.1 1600.68,419.58 1605.55,424.45 U1.9
NetC27_1: C27.1 R22.2 | length 59.1
  Top Layer w20: C27.1 982.18,414.01 R22.2
NetC27_2: C27.2 R20.2 R21.2 TP12.1 | length 380.2
  Top Layer w20: TP12.1 845,385 875,355 R21.2 913.5,439.18 948.33,474.01 R20.2
NetC28_1: C28.1 U1.14 | length 158.6
  Top Layer w12: U1.14 1700.57,552.4 C28.1
NetC29_1: C29.1 TP13.1 | length 133
  Top Layer w20: C29.1 1184.19,285.81 1215.68,254.32 TP13.1
NetC29_2: C29.2 R25.2 U1.7 | length 249.7
  Top Layer w12: C29.2 1247.18,337.18 1260,350 1290,350 1305.51,365.51 R25.2 1310.68,405.68 1355.04,450.04 U1.7
NetD1_1: D1.1 D7.1 T1.4
NetD1_3: D1.3 D7.3 T1.6
NetD3_1: D3.1 R7.2 R12.2 | length 1774.8
  Top Layer w20: R12.2 1385.68,300.12 v1(1385.68,249.01)
  Top Layer w30: D3.1 1742.39,1695.53 R7.2 v1(1745,1635)
  Bottom Layer w20: v1(1385.68,249.01) 1421.67,285 1446.68,285 1592.13,430.45 1592.13,782.13 1745,935 v1(1745,1635)
NetD3_2: D3.2 R5.1 T2.2 | length 212.1
  Top Layer w30: D3.2 1635,1845
  Top Layer w40: T2.2 1570,1958.74 R5.1 1635,1893.74 1635,1845
NetD4_1: D4.1 D7.2 L2.2 R6.1 TP9.1
NetD5_2: D5.2 Q1.5 Q1.6 Q1.7 Q1.8 Q3.5 Q3.6 Q3.7 Q3.8 T1.1 TP3.1
NetD6_2: D6.2 Q2.5 Q2.6 Q2.7 Q2.8 Q4.5 Q4.6 Q4.7 Q4.8 T1.3 TP7.1
NetD8_1: D8.1 R13.1 U1.13 | length 276.2
  Top Layer w12: U1.13 1723.19,526.81
  Top Layer w20: 1723.19,526.81 1784.01,526.81 D8.1 1786.22,546.22 1839.19,599.19 R13.1
NetD8_2: D8.2 Q1.4 Q3.4 R13.2 | length 866.7
  Top Layer w20: R13.2 1910,601.19 1910,534.17 1910.15,534.01 v1(1960.68,534.01) ; Q1.4 2288.98,580 v1(2335,580) ; Q3.4 2538.98,580 v1(2585,580)
  Bottom Layer w20: v1(1960.68,534.01) 2006.67,580 v1(2335,580) v1(2585,580)
NetD9_1: D9.1 R14.1 U1.12 | length 305.2
  Top Layer w12: U1.12 1683.78,501.22 1695,490
  Top Layer w20: 1695,490 1740,445 1770.23,445 D9.1 1786.22,413.78 1839.19,360.81 R14.1
NetD9_2: D9.2 Q2.4 Q4.4 R14.2 | length 2663.3
  Top Layer w20: R14.2 1904.01,349.01 1910,355 1910,423.86 D9.2 v1(1960.68,429.01) ; Q4.4 3401,580 v1(3445,580) ; Q2.4 3651,580 v1(3690,580)
  Bottom Layer w20: v1(1960.68,429.01) 2164.7,225 3665,225 3745,305 3745,525 v1(3690,580) v1(3445,580)
NetNT1_1: NT1.1 R5.2 R7.1 T2.4 | length 1970.3
  Top Layer w30: T2.4 1770,1950 1720,1900 R5.2 1708.74,1843.34 R7.1 1820,1732.09 1820,1655 v1(1800,1635)
  Bottom Layer w20: v1(1500,250) 1500,298.9 1620,418.9 1620,770.58 1775,925.58 1775,1610 v1(1800,1635)
NetQ5_1: Q5.1 R17.2 TP11.1 | length 217.7
  Top Layer w20: TP11.1 847.6,567.6 876.5,596.5 R17.2 916.5,596.5 932.4,612.4 Q5.1
NetQ5_3: Q5.3 R15.1 R18.2 U1.2 | length 438.8
  Top Layer w12: R18.2 1325,618.2 1325,600 1347.01,577.99 U1.2
  Top Layer w20: Q5.3 1062.24,627.24 1097.52,662.52 R18.2
NetR24_2: R24.2 U1.5 | length 117.6
  Top Layer w12: R24.2 1309.38,501.22 U1.5
NetT1_5: T1.5 T2.12
VOUT: C1.1 C2.1 C3.1 J1.1 L1.1 pad.0 R21.1 TP2.1 | length 5590.6
  Top Layer w20: R21.1 v1(1030,355)
  Signal Layer 2 w20: v1(1030,355) 1030,135 1115,50 5600,50 5665,115 pad.0
pads on no net: H1.1 H1.2 H2.1 H2.2 L1.3 L2.3 T2.1 T2.3 T2.5 T2.6 T2.7 T2.8 T2.9 T2.10

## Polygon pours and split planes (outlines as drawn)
GND on Top Layer "Top Layer-No Net 10" (solid, remove dead copper, pour order 52): 4.71,3375 5744.71,3375 5749.71,3370 5749.71,0 -0.29,0
VOUT on Top Layer "Top Layer-No Net 9" (solid, remove dead copper, pour order 42): 5750,1705 4805,1705 4745,1765 4350,1765 4350,1710 4350,1240 4405,1185 4420,1170 4450,1170 4470,1170 4545,1095 4550,1090 4550,940 4550,765 4630,685 5750,685
NetC14_2 on Top Layer "Top Layer-No Net" (solid, remove dead copper, pour order 40): 4350,2920 4350,2250 4450,2250 4455,2250 4670,2035 4705,2000 5085,2000 5090,2000 5165,1925 5195,1895 5750,1895 5750,3005 4435,3005
NetD4_1 on Top Layer "Top Layer-No Net 4" (solid, remove dead copper, pour order 36): 3665.05,2711.55 3664.8,2711.8 3664.8,2809.8 3664.8,2824.8 3665,2825 3625,2865 3620,2865 3586.63,2865 3542.06,2909.57 3539.65,2909.57 3539.65,3008.65 3620,3089 3956,3089 4040.95,3004.05 4215.95,3004.05 4300,2920 4300,2251.07 3746.07,2251.07 3745,2250 3745,2710
NetC4_1 on Top Layer "Top Layer-No Net 7" (solid, remove dead copper, pour order 38): 2105,3370 2105,2908.06 2103.06,2908.06 2075,2880 1995,2880 1990,2880 1965,2855 1965,2630 1965,2610 2010,2565 2965,2565 2965,2560 3065,2460 3065,2330 3065,1730.29 3125,1670.29 3744.69,1670.29 3745.85,1669.13 3839.13,1575.85 3839.13,1304.91 3731.96,1197.74 3755,1174.69 3755,1050 4110,1050 4300,1240 4300,1760 4245,1815 4245,1820 4195,1820 4185,1830 4155,1860 4155,1865 4155,1910 3815,2250 3730,2250 3730,2824.68 3540,3014.68 3540,3310 3480,3370
NetT1_5 on Top Layer "Top Layer-No Net 8" (solid, remove dead copper, pour order 30): 1760,2575 1955,2575 1980,2550 2540,2550 3000,2550 3050,2500 3050,2260 3050,2185 3010,2145 1760,2145
NetC17_2 on Top Layer "Top Layer-No Net 5" (solid, remove dead copper, pour order 18): 2775,760 3005,760 3005,616.69 3031.69,590 3035,590 3090,590 3095,585 3095,385 2655,385 2630,410 2630,590 2758.61,590 2775,606.39
NetC6_1 on Top Layer "Top Layer-No Net 6" (solid, remove dead copper, pour order 16): 2650,360 2625,335 2625,280 2650,255 2655,250 3070,250 3100,280 3100,335 3100,360
NetD6_2 on Top Layer "Top Layer-No Net 3" (solid, remove dead copper, pour order 10): 3035,625 3035,1565 3125,1655 3570,1655 3740,1655 3825,1570 3825,990 3825,720 3730,625
NetD5_2 on Top Layer "Top Layer-No Net 2" (solid, remove dead copper, pour order 8): 2745,980 2745,1560 2745,1570 2660,1655 2105,1655 2010,1655 1920,1565 1920,1005 1920,740 2025,635 2033.22,626.78 2745,626.78
NetC6_1 on Top Layer "Top Layer-No Net 1" (solid, remove dead copper, pour order 4): 0,1460 620,1460 955,1125 955,1020 1015,960 1435,960 1520,1045 1520,1850 1430,1940 1430,2085.47 1580.47,2085.47 1640,2145 1640,2575 1570.48,2644.52 1570,2644.52 1420.48,2644.52 1420.47,2644.53 1420.33,2644.67 1420.33,2781.5 1295.56,2781.5 1296.85,2781.5 1296.85,2863.15 1065,3095 635,3095 0,3095
GND on Bottom Layer "Bottom Layer-No Net" (solid, remove dead copper, pour order 46): 0,3370 5750,3370 5750,0 5745,-5 -5,-5
NetD1_3 on Bottom Layer "Bottom Layer-No Net 1" (solid, remove dead copper, pour order 22): 2075,2065 2045,2095 2045,2760 2205,2920 2205,3370 3795,3370 3790,3365 3790,2520 3685,2415 3230,1960 3055,1960 2180,1960
GND on Signal Layer 2 "Signal Layer 2-No Net 2" (solid, remove dead copper, pour order 48): 0,3370 5750,3370 5750,0 5,0 0,5
NetC6_1 on Signal Layer 2 "Signal Layer 2-No Net 1" (solid, remove dead copper, pour order 44): 2625,335 2625,280 2655,250 3050,250 3070,250 3090,270 3090,510 3090,590 2470,1210 1605,1210 1485,1210 1455,1180 1455,1060 1455,1040 1485,1010 1640,855 1670,825 2225,825 2440,825 2625,640
NetD1_1 on Signal Layer 2 "Signal Layer 2-No Net" (solid, remove dead copper, pour order 24): 3615,1960 3730,2075 3730,2460 3787.64,2517.64 3790,2520 3790,3370 1945,3370 1950,3365 1950,2780 1950,2430 2130,2250 2195,2185 2320,2185 2325,2185 2485,2025 2550,1960 2670,1960
GND on Signal Layer 1 "Signal Layer 1-No Net" (solid, remove dead copper, pour order 50): 0,3370 5750,3370 5750,0 5745,5 10,5

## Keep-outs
Keep-Out Layer:
  the board outline again, w7
  text ".Layer_Name" at 577,-858.49 h60

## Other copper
Top Layer:
  text ".Layer_Name" at 577,-858.49 h60
Bottom Layer:
  text ".Layer_Name" at 577,-858.49 h60

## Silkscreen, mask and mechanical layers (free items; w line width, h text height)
Top Overlay:
  text "VIN" at 100,1665 h40
  text "GND" at 100,1215 h40
  text ".PRJ_Number" at 4080,60 h60
  text ".PCB_Rev" at 4680,60 h60
  text ".Layer_Name" at 577,-858.49 h60
Bottom Overlay:
  text ".Layer_Name" at 577,-858.49 h60
Top Paste:
  text ".Layer_Name" at 577,-858.49 h60
Bottom Paste:
  text ".Layer_Name" at 577,-858.49 h60
Top Solder:
  text ".Layer_Name" at 577,-858.49 h60
  text ".Layer_Name" at 577,-858.49 h60
Bottom Solder:
  text ".Layer_Name" at 577,-858.49 h60
Drill Guide:
  text ".Layer_Name" at 577,-858.49 h60
M1 Board Outline:
  lines w7: 0,0 0,3370 5750,3370 5750,0 0,0
  lines w10: 0,0 0,3370 5750,3370 5750,0 0,0
  text ".Layer_Name" at 577,-858.49 h60
M2 Board Dimensions:
  rectangle: 0,-275 125,-150
  rectangle: 125,-400 500,-275
  lines w7: 0,-275 1000,-275 ; 125,-400 125,-150 ; 250,-400 250,-150 ; 500,-400 500,-150 ; 750,-400 750,-150 ; 0,-400 1000,-400 1000,-150 0,-150 0,-400
  text ".Layer_Name" at 577,-858.49 h60
M3 3D STEP Top:
  text ".Layer_Name" at 577,-858.49 h60
M4 3D STEP Bottom:
  text ".Layer_Name" at 577,-858.49 h60
M5 Assembly Top:
  lines w10: -292,-930.17 6308,-930.17 ; -292,-726.83 6310,-726.83 ; -292,-523.5 -292,-1133.5 3713,-1133.5 6310,-1133.5 6310,-523.5 -291.5,-523.5 -291.5,-1133.5 1284,-1133.5 ; 2173,-1133.5 2173,-523.5 ; 3440,-726.83 3440,-523.5 ; 4280,-726.83 4280,-523.5 ; 4902,-1140 4902,-937.17
  text "COMPONENTS MARKED 'DNP' SHOULD NOT BE POPULATED." at 1153.5,-318.5 h60
  text "ASSEMBLY VARIANT:" at 1153,-434 h60
  text ".VariantName" at 2189,-434 h60
  text "PCB VIEWED FROM TOP SIDE" at -228.5,-655.67 h60
  text "BOARD #:" at 2248,-655.67 h60
  text ".PRJ_Number" at 2793.5,-655.67 h60
  text "REV:" at 3638,-655.67 h60
  text ".PCB_Rev" at 3929.5,-655.67 h60
  text "SVN REV:" at 4476,-655.67 h60
  text ".VersionControl_RevNumber" at 4982,-655.67 h60
  text "TID #:" at 2248,-859 h60
  text ".TID" at 2793.5,-859 h60
  text "PLOT NAME =" at -228.5,-1064.34 h60
  text ".plot_File_Name" at 577,-1064.34 h60
  text "GENERATED    :" at 2250,-1064.34 h60
  text ".Print_Date" at 3119.5,-1064.34 h60
  text ".Print_Time" at 3848.5,-1064.34 h60
  text "TEXAS INSTRUMENTS" at 5113,-1064.34 h60
M6 Assembly Bottom:
  lines w10: -292.5,-727.33 6309.5,-727.33 ; -290.5,-930.67 6309.5,-930.67 ; 1115.5,-1140.5 1115.5,-937.67 ; 1737.5,-727.33 1737.5,-524 ; 2577.5,-727.33 2577.5,-524 ; 3844.5,-1134 3844.5,-524 ; 4733.5,-1134 6309,-1134 6309,-524 -292.5,-524 -292.5,-1134 2304.5,-1134 6309.5,-1134 6309.5,-524
  text "COMPONENTS MARKED 'DNP' SHOULD NOT BE POPULATED." at 6102,-318 h60
  text ".VariantName" at 5058,-434 h60
  text "ASSEMBLY VARIANT:" at 6097,-434 h60
  text ".VersionControl_RevNumber" at 1035.5,-656.17 h60
  text "SVN REV:" at 1541.5,-656.17 h60
  text ".PCB_Rev" at 2088,-656.17 h60
  text "REV:" at 2379.5,-656.17 h60
  text ".PRJ_Number" at 3224,-656.17 h60
  text "BOARD #:" at 3769.5,-656.17 h60
  text "PCB VIEWED FROM BOTTOM SIDE" at 6246,-656.17 h60
  text ".TID" at 3224,-859.5 h60
  text "TID #:" at 3769.5,-859.5 h60
  text "TEXAS INSTRUMENTS" at 904.5,-1064.84 h60
  text ".Print_Time" at 2169,-1064.84 h60
  text ".Print_Date" at 2898,-1064.84 h60
  text "GENERATED    :" at 3767.5,-1064.84 h60
  text ".plot_File_Name" at 5440.5,-1064.84 h60
  text "PLOT NAME =" at 6246,-1064.84 h60
M9 Title Sheet:
  drawing of 57 lines, arcs and shapes, not listed
  text "1" at 739.84,8036.5 h70
  text "2" at 3235.5,8036.5 h70
  text "3" at 5724.84,8036.5 h70
  text "4" at 8231.51,8036.5 h70
  text "5" at 10730.5,8036.5 h70
  text "6" at 13235.5,8036.5 h70
  text "A" at -416.5,6893.5 h70
  text "A" at 14383.5,6893.5 h70
  text "B" at -416.5,4513.5 h70
  text "B" at 14383.5,4513.5 h70
  text "C" at -416.5,2138.5 h70
  text "C" at 14383.5,2138.5 h70
  text "PROJECT TITLE:" at 11343.5,277.5 h45
  text ".PRJ_Title" at 11393.5,144.17 h70
  text "DESIGNED FOR:" at 11343.5,-23.5 h45
  text ".PRJ_Customer" at 11393.5,-163.5 h70
  text "D" at -416.5,-231.5 h70
  text "D" at 14383.5,-231.5 h70
  text "FILE NAME:" at 11343.5,-323.5 h45
  text ".PCB_File_Name_No_Path" at 11393.5,-443.5 h70
  text "Texas Instruments (TI) and/or its licensors do not warrant the accuracy or completeness of this specification" at 6374,-605.34 h45
  text "ENGINEER:" at 11343.5,-613.5 h45
  text "LAYOUT BY:" at 12848.5,-613.5 h45
  text "or any information contained therein. TI and/or its licensors do not warrant that this design will meet" at 6329.01,-718 h45
  text ".PRJ_Engineer" at 11393.5,-768.49 h70
  text ".PCB_Layout" at 12899,-768.49 h70
  text "the specifications, will be suitable for your application or fit for any particular purpose, or will operate in" at 6329.01,-830.67 h45
  text ".Layer_Name" at 577,-858.49 h60
  text "ALTIUM DESIGNER VERSION:" at 12848.5,-923.5 h45
  text "an implementation. TI and/or its licensors do not warrant that the design is production worthy. You should" at 6329.01,-943.33 h45
  text "completely validate and test your design implementation to confirm the system functionality for your application." at 6374,-1056 h45
  text ".print_Scale" at 11393.5,-1056.83 h70
  text ".Application_BuildNumber" at 12899,-1056.83 h70
  text "1" at 739.84,-1263.5 h70
  text "2" at 3235.5,-1263.5 h70
  text "3" at 5724.84,-1263.5 h70
  text "4" at 8231.51,-1263.5 h70
  text "5" at 10730.5,-1263.5 h70
  text "6" at 13235.5,-1263.5 h70
M10 Fab Notes:
  drawing of 185 lines, arcs and shapes, not listed
  text "DESIGN INFORMATION" at 12381.02,5910 h60
  text "MIN. TRACK WIDTH:" at 11736.46,5730 h60
  text "8" at 12832.7,5730 h60
  text "MIL" at 12987.46,5730 h60
  text "MIN. CLEARANCE:" at 11736.46,5598 h60
  text "0.2" at 12772.7,5598 h60
  text "mm" at 12987.46,5598 h60
  text "MIN. VIA PAD SIZE:" at 11736.46,5466 h60
  text "24" at 12802.71,5466 h60
  text "MIL" at 12987.46,5466 h60
  text "0.05mm (2MIL)" at 12431.46,5324.29 h60
  text "MINIMUM ANNULAR RING" at 11407.23,5320 h60
  text "EXTERNAL" at 13139.46,5320 h60
  text "PER" at 11607.23,5202 h60
  text "IPC-D-275 CLASS 2 LEVEL C" at 11827.23,5202 h60
  text "MIL, HOLES" at 13315.46,5089.71 h60
  text "+/-" at 12923,5089 h60
  text "+/-" at 13777,5089 h60
  text "REGISTRATION TOLERANCES:" at 11407.23,5084 h60
  text "METAL" at 12607,5084 h60
  text "5" at 13183.2,5084 h60
  text "3" at 14016.2,5084 h60
  text "MIL" at 14132.46,5084 h60
  text "MATERIAL:" at 11332.46,4874.54 h60
  text "FR-4 High Tg" at 12318.9,4734.21 h60
  text "FR-408" at 11753.46,4725.64 h60
  text "X" at 12165.46,4725.64 h60
  text "OTHER" at 13241.46,4725.64 h60
  text "62 MIL (1.6mm) +/-10%" at 12073.56,4562.92 h60
  text "THICKNESS:" at 11407.23,4558.64 h60
  text "X" at 11945.4,4558.64 h60
  text "OTHER" at 13358.46,4558.64 h60
  text "TOLERANCE:" at 11407.23,4400.64 h60
  text "X" at 12246.53,4400.64 h60
  text "ANSI IPC-6012 TYPE 3 CLASS 2" at 12433.48,4400.64 h60
  text "OTHER +/-" at 12433.46,4244.64 h60
  text "BOW & TWIST:" at 11407.23,4087.64 h60
  text "X" at 12246.53,4087.64 h60
  text "ANSI IPC-6012 TYPE 3 CLASS 2" at 12433.48,4087.64 h60
  text "OTHER +/-" at 12433.46,3929.13 h60
  text "DRILLING:" at 11332.46,3790.64 h60
  text "REFERENCE:" at 11407.23,3673.64 h60
  text "X" at 12055.46,3673.64 h60
  text "AS SHOWN" at 12242.46,3673.64 h60
  text "X" at 12956.46,3673.64 h60
  text "NC_DRILL FILES" at 13093.46,3673.64 h60
  text "PTH MIN COPPER THICKNESS:" at 11407.23,3515.64 h60
  text "X" at 12757.46,3515.64 h60
  text "1MIL" at 12894.46,3515.64 h60
  text "OTHER" at 13391.46,3515.64 h60
  text "BOARD FINISH:" at 11332.46,3356.64 h60
  text "SILKSCREEN:" at 11487.68,3238.64 h60
  text "X" at 12436.46,3238.64 h60
  text "TOP" at 12562.46,3238.64 h60
  text "X" at 12946.46,3238.64 h60
  text "BOTTOM" at 13073.46,3238.64 h60
  text "SILKSCREEN COLOR:" at 11487.68,3071.64 h60
  text "X" at 12435.42,3071.64 h60
  text "WHITE" at 12562.46,3071.64 h60
  text "OTHER" at 13073.46,3071.64 h60
  text "SOLDER RESIST COLOR:" at 11487.68,2901.64 h60
  text "X" at 12650,2755 h60
  text "GREEN" at 12182.46,2742.44 h60
  text "BLUE" at 12773.46,2742.44 h60
  text "OTHER" at 13311.46,2742.44 h60
  text "IMMERSION GOLD (ENIG)" at 12393.46,2553.92 h60
  text "ENEPIG" at 13731,2550.64 h60
  text "SURFACE FINISH:" at 11332.46,2549.64 h60
  text "IMM. TIN/SILVER OR EQUIV" at 11662,2392.64 h60
  text "OTHER" at 13093.46,2392.64 h60
  text "X" at 11500,2390 h60
  text "ARRAY/PANEL:" at 11332.46,2213.64 h60
  text "CUT AND TRIM PER MECH LAYER 1" at 12393.46,2209.35 h60
  text "N.C. ROUTE" at 12393.46,2057.64 h60
  text "X" at 13072.46,2057.64 h60
  text "V. SCORE" at 13259.46,2057.64 h60
  text "CERTIFICATION:" at 11332.46,1920.64 h60
  text "MATERIALS AND WORKMANSHIP FOR ALL PCBS" at 12057.46,1920.64 h60
  text "TO MEET OR EXCEED THE REQUIREMENTS OF:" at 12057.46,1822.64 h60
  text "X" at 11683.96,1686.13 h60
  text "ANSI IPC-A-600F CLASS ->" at 11822.96,1686.13 h60
  text "X" at 13462.02,1686.13 h60
  text "2" at 13580.96,1686.14 h60
  text "1" at 13265.96,1684.64 h60
  text "3" at 13934.96,1684.64 h60
  text "X" at 11686.02,1526.64 h60
  text "UL 94V-0" at 11822.96,1526.64 h60
  text "X" at 12498.02,1526.64 h60
  text "RoHS" at 12634.96,1526.64 h60
  text "OTHER" at 13279.36,1526.64 h60
  text "PER ORDER" at 13676.42,1526.64 h60
  text "ADDITIONAL REQUIREMENTS:" at 11332.46,1385.64 h60
  text "MICROSECTION:" at 11407.23,1270.64 h60
  text "YES" at 12312.96,1270.64 h60
  text "REQUIRED" at 13174.46,1114.49 h60
  text "BARE BOARD ELEC. TEST:" at 11407.23,1111.64 h60
  text "NONE" at 12712.96,1111.64 h60
  text "X" at 13047.46,1111.64 h60
  text "PER ORDER" at 13766.46,1111.64 h60
  text "MANUFACTURER'S UL:" at 11407.23,954.64 h60
  text "RAIL" at 12572.96,950.35 h60
  text "METAL" at 13064.77,950.35 h60
  text "X" at 13440,950 h60
  text "SILK" at 13576.46,950.35 h60
  text ".Layer_Name" at 577,-858.49 h60
M11 Gerber Information:
  lines w10: -292,-930.17 6308,-930.17 ; -292,-726.83 6310,-726.83 ; -292,-523.5 -292,-1133.5 3713,-1133.5 6310,-1133.5 6310,-523.5 -291.5,-523.5 -291.5,-1133.5 1284,-1133.5 ; 2173,-1133.5 2173,-523.5 ; 3440,-726.83 3440,-523.5 ; 4280,-726.83 4280,-523.5 ; 4902,-1140 4902,-937.17
  text "ALL ARTWORK VIEWED FROM TOP SIDE" at -228.5,-655.67 h60
  text "BOARD #:" at 2248,-655.67 h60
  text ".PRJ_Number" at 2793.5,-655.67 h60
  text "REV:" at 3638,-655.67 h60
  text ".PCB_Rev" at 3929.5,-655.67 h60
  text "SVN REV:" at 4476,-655.67 h60
  text ".VersionControl_RevNumber" at 4982,-655.67 h60
  text "LAYER NAME =" at -228.5,-858.49 h60
  text "TID #:" at 2248,-859 h60
  text ".TID" at 2793.5,-859 h60
  text "PLOT NAME =" at -228.5,-1064.34 h60
  text ".plot_File_Name" at 577,-1064.34 h60
  text "GENERATED    :" at 2250,-1064.34 h60
  text ".Print_Date" at 3119.5,-1064.34 h60
  text ".Print_Time" at 3848.5,-1064.34 h60
  text "TEXAS INSTRUMENTS" at 5113,-1064.34 h60
M12 Stackup:
  drawing of 295 lines, arcs and shapes, not listed
  text "Layer" at 9780.35,7840 h60
  text "Name" at 10190.26,7840 h60
  text "Material" at 11130,7840 h60
  text "Thickness" at 11989.77,7840 h60
  text "Constant" at 12639.6,7840 h60
  text "Board Layer Stack" at 13209.46,7840 h60
  text "1" at 9780.35,7720 h60
  text "Top Overlay" at 10190.26,7720 h60
  text "2" at 9780.35,7600 h60
  text "Top Solder" at 10190.26,7600 h60
  text "Solder Resist" at 11130,7600 h60
  text "0.40mil" at 11989.77,7600 h60
  text "3.5" at 12639.6,7600 h60
  text "3" at 9780.35,7480 h60
  text "Top Layer" at 10190.26,7480 h60
  text "Copper" at 11130,7480 h60
  text "2.80mil" at 11989.77,7480 h60
  text "4" at 9780.35,7360 h60
  text "Dielectric1" at 10190.26,7360 h60
  text "FR-4" at 11130,7360 h60
  text "59.20mil" at 11989.77,7360 h60
  text "4.8" at 12639.6,7360 h60
  text "5" at 9780.35,7240 h60
  text "Signal Layer 1" at 10190.26,7240 h60
  text "Copper" at 11130,7240 h60
  text "2.80mil" at 11989.77,7240 h60
  text "6" at 9780.35,7120 h60
  text "Dielectric 3" at 10190.26,7120 h60
  text "5.00mil" at 11989.77,7120 h60
  text "4.2" at 12639.6,7120 h60
  text "7" at 9780.35,7000 h60
  text "Signal Layer 2" at 10190.26,7000 h60
  text "Copper" at 11130,7000 h60
  text "2.80mil" at 11989.77,7000 h60
  text "8" at 9780.35,6880 h60
  text "Dielectric 2" at 10190.26,6880 h60
  text "10.00mil" at 11989.77,6880 h60
  text "4.2" at 12639.6,6880 h60
  text "9" at 9780.35,6760 h60
  text "Bottom Layer" at 10190.26,6760 h60
  text "Copper" at 11130,6760 h60
  text "2.80mil" at 11989.77,6760 h60
  text "10" at 9780.35,6640 h60
  text "Bottom Solder" at 10190.26,6640 h60
  text "Solder Resist" at 11130,6640 h60
  text "0.40mil" at 11989.77,6640 h60
  text "3.5" at 12639.6,6640 h60
  text "11" at 9780.35,6520 h60
  text "Bottom Overlay" at 10190.26,6520 h60
  text ".Layer_Name" at 577,-858.49 h60
M13 Component Bodies Top:
  text ".Layer_Name" at 577,-858.49 h60
M14 Component Bodies Bottom:
  text ".Layer_Name" at 577,-858.49 h60
M15 Courtyards Top:
  text ".Layer_Name" at 577,-858.49 h60
M16 Courtyards Bottom:
  text ".Layer_Name" at 577,-858.49 h60
Drill Drawing:
  circle w1: c7766.73,5726.81 r18.09
  circle w1: c7766.73,5726.81 r30.15
  circle w1: c7766.73,5365.01 r30.15
  lines w1: 7736.58,3706.72 7796.88,3706.72 7796.88,3767.02 7736.58,3767.02 7736.58,3706.72 ; 7736.58,3917.77 7766.73,3887.62 7796.88,3917.77 7766.73,3947.93 7736.58,3917.77 ; 7736.58,4083.6 7751.66,4083.6 7766.73,4068.53 7781.81,4083.6 7796.88,4083.6 7781.81,4098.68 7796.88,4113.75 7781.81,4113.75 7766.73,4128.83 7751.66,4113.75 7736.58,4113.75 7751.66,4098.68 7736.58,4083.6 ; 7736.58,4249.43 7736.58,4264.51 7751.66,4279.58 7736.58,4294.66 7736.58,4309.73 7751.66,4309.73 7766.73,4294.66 7781.81,4309.73 7796.88,4309.73 7796.88,4294.66 7781.81,4279.58 7796.88,4264.51 7796.88,4249.43 7781.81,4249.43 7766.73,4264.51 7751.66,4249.43 7736.58,4249.43 ; 7736.58,4445.41 7751.66,4445.41 7751.66,4430.34 7781.81,4430.34 7781.81,4445.41 7796.88,4445.41 7796.88,4475.56 7781.81,4475.56 7781.81,4490.64 7751.66,4490.64 7751.66,4475.56 7736.58,4475.56 7736.58,4445.41 ; 7736.58,4611.24 7766.73,4626.32 7796.88,4611.24 7781.81,4641.39 7796.88,4671.54 7766.73,4656.47 7736.58,4671.54 7751.66,4641.39 7736.58,4611.24 ; 7736.58,4807.22 7751.66,4807.22 7766.73,4792.14 7781.81,4807.22 7796.88,4807.22 7781.81,4822.29 7796.88,4837.37 7781.81,4837.37 7766.73,4852.45 7751.66,4837.37 7736.58,4837.37 7751.66,4822.29 7736.58,4807.22 ; 7736.58,5033.35 7796.88,5033.35 7766.73,4973.05 7736.58,5033.35 ; 7736.58,5214.25 7796.88,5214.25 7766.73,5153.95 7736.58,5214.25 ; 7736.58,5515.76 7796.88,5515.76 7796.88,5576.06 7736.58,5576.06 7736.58,5515.76 ; 7748.64,3718.78 7784.82,3718.78 7784.82,3754.96 7748.64,3754.96 7748.64,3718.78 ; 7748.64,4089.63 7757.69,4089.63 7766.73,4080.59 7775.78,4089.63 7784.82,4089.63 7775.78,4098.68 7784.82,4107.72 7775.78,4107.72 7766.73,4116.77 7757.69,4107.72 7748.64,4107.72 7757.69,4098.68 7748.64,4089.63 ; 7748.64,5021.29 7784.82,5021.29 7766.73,4985.11 7748.64,5021.29
  lines w12: 7655.06,3652.45 10275.15,3652.45 ; 7655.06,5823.3 10275.15,5823.3 ; 8111.19,3471.55 8111.19,6004.2 ; 8552.46,3471.55 8552.46,6004.2 ; 9375.58,3471.55 9375.58,6004.2 ; 9725.5,3471.55 9725.5,6004.2 ; 7655.06,3471.55 10275.15,3471.55 10275.15,6004.2 7655.06,6004.2 7655.06,3471.55
  text "Symbol" at 7763.61,5877.57 h90.26
  text "Quantity" at 8165.46,5877.57 h90.26
  text "Finished Hole Size" at 8606.73,5877.57 h90.26
  text "Plated" at 9429.85,5877.57 h90.26
  text "Hole Type" at 9779.77,5877.57 h90.26
  text "139" at 8165.46,5696.66 h75.21
  text "16.00mil (0.406mm)" at 8606.73,5696.66 h75.21
  text "PTH" at 9429.85,5696.66 h75.21
  text "Round" at 9779.77,5696.66 h75.21
  text "1" at 8165.46,5515.76 h75.21
  text "30.00mil (0.762mm)" at 8606.73,5515.76 h75.21
  text "PTH" at 9429.85,5515.76 h75.21
  text "Round" at 9779.77,5515.76 h75.21
  text "12" at 8165.46,5334.86 h75.21
  text "33.46mil (0.850mm)" at 8606.73,5334.86 h75.21
  text "PTH" at 9429.85,5334.86 h75.21
  text "Round" at 9779.77,5334.86 h75.21
  text "8" at 8165.46,5153.95 h75.21
  text "35.43mil (0.900mm)" at 8606.73,5153.95 h75.21
  text "PTH" at 9429.85,5153.95 h75.21
  text "Round" at 9779.77,5153.95 h75.21
  text "13" at 8165.46,4973.05 h75.21
  text "40.00mil (1.016mm)" at 8606.73,4973.05 h75.21
  text "PTH" at 9429.85,4973.05 h75.21
  text "Round" at 9779.77,4973.05 h75.21
  text "9" at 8165.46,4792.14 h75.21
  text "51.18mil (1.300mm)" at 8606.73,4792.14 h75.21
  text "PTH" at 9429.85,4792.14 h75.21
  text "Round" at 9779.77,4792.14 h75.21
  text "2" at 8165.46,4611.24 h75.21
  text "78.74mil (2.000mm)" at 8606.73,4611.24 h75.21
  text "PTH" at 9429.85,4611.24 h75.21
  text "Round" at 9779.77,4611.24 h75.21
  text "4" at 8165.46,4430.34 h75.21
  text "110.24mil (2.800mm)" at 8606.73,4430.34 h75.21
  text "PTH" at 9429.85,4430.34 h75.21
  text "Round" at 9779.77,4430.34 h75.21
  text "2" at 8165.46,4249.43 h75.21
  text "153.54mil (3.900mm)" at 8606.73,4249.43 h75.21
  text "PTH" at 9429.85,4249.43 h75.21
  text "Round" at 9779.77,4249.43 h75.21
  text "2" at 8165.46,4068.53 h75.21
  text "188.00mil (4.775mm)" at 8606.73,4068.53 h75.21
  text "PTH" at 9429.85,4068.53 h75.21
  text "Round" at 9779.77,4068.53 h75.21
  text "1" at 8165.46,3887.62 h75.21
  text "78.74mil (2.000mm)" at 8606.73,3887.62 h75.21
  text "PTH" at 9429.85,3887.62 h75.21
  text "Slot" at 9779.77,3887.62 h75.21
  text "1" at 8165.46,3706.72 h75.21
  text "157.48mil (4.000mm)" at 8606.73,3706.72 h75.21
  text "PTH" at 9429.85,3706.72 h75.21
  text "Slot" at 9779.77,3706.72 h75.21
  text "194 Total" at 8165.46,3525.82 h75.21
  text ".Layer_Name" at 577,-858.49 h60

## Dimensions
0,-400 to 1000,-400 on M2 Board Dimensions
0,0 to 0,3370 on M2 Board Dimensions
0,0 to 5750,0 on M2 Board Dimensions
